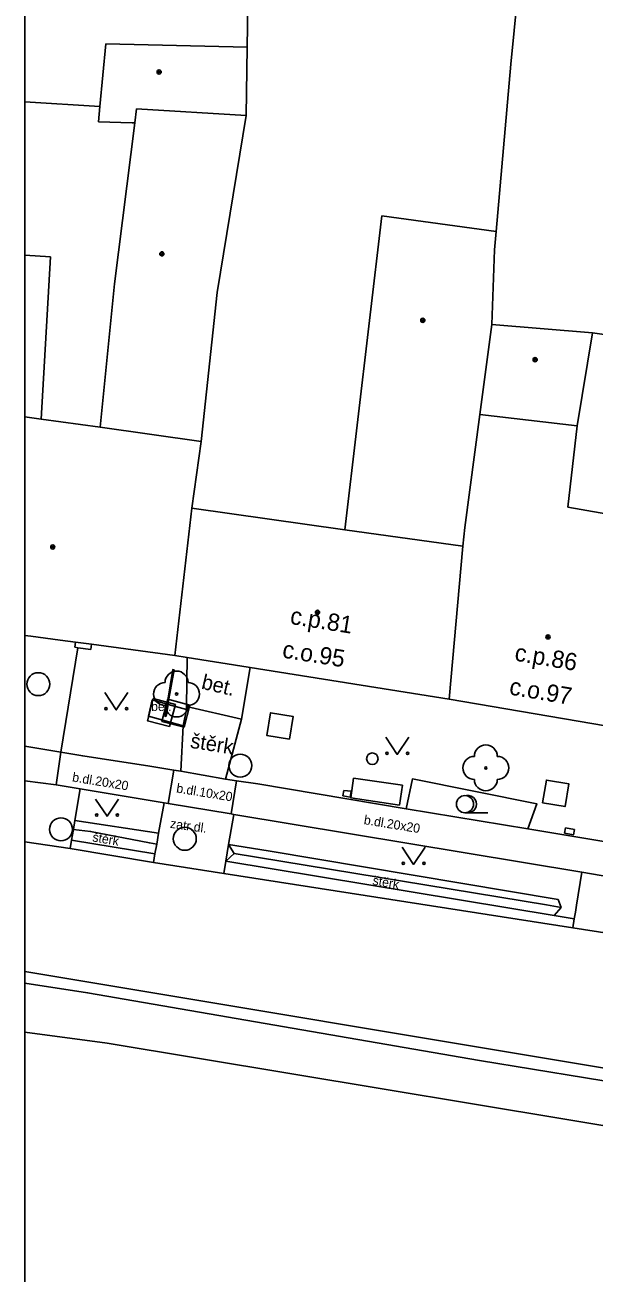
# Model space of a CAD drawing. Extents: x -591353 to -591106, y -1167325 to -1167155.
# Drawn here: x -591352.6 to -591327.7, y -1167266.9 to -1167212.5 of the extents above; entities that cross this region are included whole.
import ezdxf

# ---------------------------------------------------------------- set-up
doc = ezdxf.new("R2010")
doc.units = 0
for name, color, linetype in [('Level 22', 7, 'Continuous'), ('Level 24', 7, 'Continuous'), ('Level 26', 7, 'Continuous'), ('Level 27', 7, 'Continuous'), ('Level 31', 7, 'Continuous'), ('Level 36', 7, 'Continuous'), ('Level 39', 7, 'Continuous'), ('Vrstva 10', 7, 'Continuous'), ('Vrstva 11', 7, 'Continuous'), ('Vrstva 21', 7, 'Continuous'), ('Vrstva 40', 7, 'Continuous'), ('Vrstva 46', 7, 'Continuous'), ('Vrstva 5', 7, 'Continuous'), ('Vrstva 51', 7, 'Continuous'), ('Vrstva 6', 7, 'Continuous'), ('Vrstva 63', 7, 'Continuous'), ('Vrstva 7', 7, 'Continuous')]:
    doc.layers.add(name, color=color, linetype=linetype)

msp = doc.modelspace()

# ---------------------------------------------------------------- linework, layer by layer
at = {"layer": 'Level 22'}
for centre in [(-591345.96, -1167241.69), (-591332.47, -1167244.91)]:
    msp.add_circle(centre, 0.05, dxfattribs=at)
for centre, start, end in [((-591345.96, -1167241.19), 0, 180), ((-591346.46, -1167241.69), 90, 270), ((-591345.46, -1167241.69), 270, 90), ((-591345.96, -1167242.19), 180, 0), ((-591332.47, -1167244.41), 0, 180), ((-591332.97, -1167244.91), 90, 270), ((-591331.97, -1167244.91), 270, 90), ((-591332.47, -1167245.41), 180, 0)]:
    msp.add_arc(centre, 0.5, start, end, dxfattribs=at)
at = {"layer": 'Level 24'}
for points in [[(-591350.4, -1167239.65), (-591350.37, -1167239.43)], [(-591350.4, -1167239.65), (-591350.27, -1167239.67)], [(-591350.27, -1167239.67), (-591349.7, -1167239.75)], [(-591349.7, -1167239.75), (-591349.67, -1167239.52)], [(-591338.24, -1167245.36), (-591338.36, -1167246.22)], [(-591338.24, -1167245.36), (-591336.1, -1167245.67)], [(-591336.1, -1167245.67), (-591336.23, -1167246.53)], [(-591338.7, -1167246.13), (-591338.66, -1167245.89)], [(-591338.7, -1167246.13), (-591338.38, -1167246.18)], [(-591338.66, -1167245.89), (-591338.34, -1167245.93)], [(-591338.38, -1167246.18), (-591338.34, -1167245.93)], [(-591338.36, -1167246.22), (-591336.23, -1167246.53)], [(-591329, -1167247.53), (-591329.04, -1167247.76)], [(-591329.04, -1167247.76), (-591328.64, -1167247.83)], [(-591329, -1167247.53), (-591328.6, -1167247.6)], [(-591328.6, -1167247.6), (-591328.64, -1167247.83)]]:
    msp.add_lwpolyline(points, dxfattribs=at)
at = {"layer": 'Level 26'}
for points in [[(-591346.264, -1167243.111), (-591346.009, -1167242.144), (-591346.976, -1167241.889), (-591347.231, -1167242.856)], [(-591345.634, -1167243.141), (-591345.379, -1167242.174), (-591346.346, -1167241.919), (-591346.601, -1167242.886)], [(-591341.039, -1167243.656), (-591340.874, -1167242.669), (-591341.861, -1167242.504), (-591342.026, -1167243.491)], [(-591329.996, -1167246.43), (-591329.01, -1167246.596), (-591328.844, -1167245.61), (-591329.83, -1167245.444)]]:
    msp.add_lwpolyline(points, close=True, dxfattribs=at)
at = {"layer": 'Level 27'}
for centre in [(-591351.99, -1167241.26), (-591343.18, -1167244.81), (-591351, -1167247.59), (-591345.6, -1167248)]:
    msp.add_circle(centre, 0.5, dxfattribs=at)
at = {"layer": 'Level 31'}
msp.add_circle((-591337.42, -1167244.51), 0.25, dxfattribs=at)
at = {"layer": 'Level 36'}
msp.add_line((-591333.38, -1167246.865), (-591332.38, -1167246.865), dxfattribs=at)
for points in [[(-591349.09, -1167241.63), (-591348.59, -1167242.38), (-591348.09, -1167241.63)], [(-591336.83, -1167243.57), (-591336.33, -1167244.32), (-591335.83, -1167243.57)], [(-591349.49, -1167246.27), (-591348.99, -1167247.02), (-591348.49, -1167246.27)], [(-591336.12, -1167248.37), (-591335.62, -1167249.12), (-591335.12, -1167248.37)]]:
    msp.add_lwpolyline(points, dxfattribs=at)
for centre, radius in [((-591349.04, -1167242.33), 0.05), ((-591348.141, -1167242.33), 0.05), ((-591336.78, -1167244.27), 0.05), ((-591335.881, -1167244.27), 0.05), ((-591333.38, -1167246.49), 0.375), ((-591349.44, -1167246.97), 0.05), ((-591348.541, -1167246.97), 0.05), ((-591336.07, -1167249.07), 0.05), ((-591335.171, -1167249.07), 0.05)]:
    msp.add_circle(centre, radius, dxfattribs=at)
msp.add_arc((-591333.255, -1167246.49), 0.375, 260.4059, 99.5941, dxfattribs=at)
at = {"layer": 'Level 39'}
for centre, radius in [((-591346.72, -1167214.57), 0.09), ((-591346.72, -1167214.57), 0.0398), ((-591346.6, -1167222.5), 0.09), ((-591346.6, -1167222.5), 0.0398), ((-591335.22, -1167225.4), 0.09), ((-591335.22, -1167225.4), 0.0398), ((-591330.32, -1167227.11), 0.09), ((-591330.32, -1167227.11), 0.0398), ((-591351.36, -1167235.28), 0.09), ((-591351.36, -1167235.28), 0.0398), ((-591339.81, -1167238.13), 0.09), ((-591339.81, -1167238.13), 0.0398), ((-591329.76, -1167239.2), 0.09), ((-591329.76, -1167239.2), 0.0398)]:
    msp.add_circle(centre, radius, dxfattribs=at)
at = {"layer": 'Vrstva 10'}
for p, q in [((-591350.6, -1167248.43), (-591352.572, -1167248.129)), ((-591352.572, -1167253.793), (-591321.23, -1167259.02))]:
    msp.add_line(p, q, dxfattribs=at)
for points in [[(-591346.97, -1167249.04), (-591350.6, -1167248.43)], [(-591343.9, -1167249.51), (-591346.97, -1167249.04)], [(-591328.67, -1167251.89), (-591343.9, -1167249.51)], [(-591323.92, -1167252.63), (-591328.67, -1167251.89)]]:
    msp.add_lwpolyline(points, dxfattribs=at)
at = {"layer": 'Vrstva 11'}
for p, q in [((-591352.572, -1167243.964), (-591351.01, -1167244.23)), ((-591351.21, -1167245.65), (-591352.572, -1167245.475))]:
    msp.add_line(p, q, dxfattribs=at)
for points in [[(-591352.572, -1167222.555), (-591351.461, -1167222.633), (-591351.87, -1167229.7)], [(-591350.27, -1167239.67), (-591351.01, -1167244.23)], [(-591345.5, -1167240.09), (-591345.52, -1167242.23)], [(-591346.07, -1167240.64), (-591346.125, -1167240.626), (-591346.36, -1167242.05), (-591346.37, -1167242.13)], [(-591342.75, -1167240.53), (-591343.13, -1167242.79)], [(-591347.03, -1167241.95), (-591347.18, -1167242.65)], [(-591347.03, -1167241.95), (-591346.37, -1167242.13)], [(-591346.37, -1167242.13), (-591346.463, -1167242.657), (-591346.41, -1167242.67)], [(-591346.33, -1167242.14), (-591345.52, -1167242.36)], [(-591345.52, -1167242.36), (-591345.67, -1167243.07)], [(-591345.52, -1167242.23), (-591345.52, -1167242.36)], [(-591345.52, -1167242.23), (-591343.13, -1167242.79)], [(-591347.18, -1167242.65), (-591345.67, -1167243.07)], [(-591345.78, -1167245.06), (-591345.67, -1167243.07)], [(-591343.13, -1167242.79), (-591343.83, -1167245.4)], [(-591351.01, -1167244.23), (-591351.21, -1167245.65)], [(-591351.01, -1167244.23), (-591350.05, -1167244.39), (-591347.13, -1167244.84), (-591346.08, -1167245.01)], [(-591346.32, -1167246.46), (-591346.08, -1167245.01)], [(-591346.08, -1167245.01), (-591345.78, -1167245.06)], [(-591345.78, -1167245.06), (-591343.83, -1167245.4)], [(-591351.21, -1167245.65), (-591350.16, -1167245.83)], [(-591350.4, -1167247.21), (-591350.16, -1167245.83)], [(-591350.16, -1167245.83), (-591346.5, -1167246.43)], [(-591343.34, -1167245.48), (-591343.83, -1167245.4)], [(-591343.34, -1167245.48), (-591343.58, -1167246.92)], [(-591335.95, -1167246.69), (-591342.42, -1167245.61), (-591343.34, -1167245.48)], [(-591346.5, -1167246.43), (-591346.74, -1167247.76)], [(-591346.5, -1167246.43), (-591346.32, -1167246.46)], [(-591346.32, -1167246.46), (-591343.58, -1167246.92)], [(-591343.69, -1167248.25), (-591343.46, -1167246.94)], [(-591343.58, -1167246.92), (-591343.46, -1167246.94)], [(-591343.46, -1167246.94), (-591328.28, -1167249.46)], [(-591330.64, -1167247.57), (-591335.95, -1167246.69)], [(-591350.46, -1167247.59), (-591350.4, -1167247.21)], [(-591346.74, -1167247.76), (-591350.4, -1167247.21)], [(-591350.54, -1167248.06), (-591350.46, -1167247.59)], [(-591346.82, -1167248.24), (-591347.14, -1167248.18), (-591349.71, -1167247.68), (-591350.46, -1167247.59)], [(-591346.74, -1167247.76), (-591346.82, -1167248.24)], [(-591326.45, -1167248.27), (-591330.64, -1167247.57)], [(-591350.6, -1167248.43), (-591350.54, -1167248.06)], [(-591350.54, -1167248.06), (-591346.9, -1167248.66)], [(-591346.82, -1167248.24), (-591346.9, -1167248.66)], [(-591343.81, -1167248.98), (-591343.69, -1167248.25)], [(-591343.45, -1167248.64), (-591343.69, -1167248.25)], [(-591343.69, -1167248.25), (-591341.96, -1167248.53), (-591329.32, -1167250.65), (-591329.19, -1167251)], [(-591346.9, -1167248.66), (-591346.97, -1167249.04)], [(-591343.9, -1167249.51), (-591343.81, -1167248.98)], [(-591343.45, -1167248.64), (-591343.81, -1167248.98)], [(-591343.81, -1167248.98), (-591329.49, -1167251.35)], [(-591343.45, -1167248.64), (-591329.83, -1167250.88), (-591329.19, -1167251)], [(-591328.28, -1167249.46), (-591328.51, -1167250.89)], [(-591328.28, -1167249.46), (-591326.68, -1167249.73)], [(-591329.19, -1167251), (-591329.49, -1167251.35)], [(-591328.56, -1167251.2), (-591328.61, -1167251.49)], [(-591328.51, -1167250.89), (-591328.56, -1167251.2)], [(-591329.49, -1167251.35), (-591328.61, -1167251.49)], [(-591328.61, -1167251.49), (-591328.67, -1167251.89)], [(-591321.18, -1167259.55), (-591332.74, -1167257.67), (-591349.84, -1167254.71), (-591352.572, -1167254.294)], [(-591352.572, -1167256.425), (-591348.99, -1167256.91), (-591320.97, -1167261.56)]]:
    msp.add_lwpolyline(points, dxfattribs=at)
at = {"layer": 'Vrstva 21'}
msp.add_lwpolyline([(-591335.95, -1167246.69), (-591335.67, -1167245.39), (-591330.24, -1167246.48), (-591330.64, -1167247.57)], dxfattribs=at)
at = {"layer": 'Vrstva 5'}
for p, q in [((-591351.87, -1167229.7), (-591352.572, -1167229.602)), ((-591352.572, -1167239.136), (-591352.32, -1167239.17))]:
    msp.add_line(p, q, dxfattribs=at)
for points in [[(-591349.05, -1167213.34), (-591349.31, -1167216.07)], [(-591342.88, -1167213.49), (-591349.05, -1167213.34)], [(-591342.93, -1167216.47), (-591342.88, -1167213.49)], [(-591349.31, -1167216.07), (-591349.37, -1167216.75)], [(-591347.7, -1167216.17), (-591347.78, -1167216.79)], [(-591342.93, -1167216.47), (-591347.7, -1167216.17)], [(-591344.19, -1167224.19), (-591342.93, -1167216.47)], [(-591349.37, -1167216.75), (-591347.9, -1167216.79)], [(-591347.78, -1167216.79), (-591348.67, -1167223.81)], [(-591347.9, -1167216.79), (-591347.78, -1167216.79)], [(-591337, -1167220.84), (-591338.62, -1167234.53)], [(-591332.02, -1167221.52), (-591337, -1167220.84)], [(-591332.09, -1167222.33), (-591332.02, -1167221.52)], [(-591332.21, -1167225.58), (-591332.09, -1167222.33)], [(-591348.67, -1167223.81), (-591349.29, -1167230.06)], [(-591344.89, -1167230.68), (-591344.19, -1167224.19)], [(-591332.73, -1167229.51), (-591332.21, -1167225.58)], [(-591327.82, -1167225.94), (-591332.21, -1167225.58)], [(-591328.48, -1167229.99), (-591327.82, -1167225.94)], [(-591333.39, -1167234.43), (-591332.73, -1167229.51)], [(-591332.73, -1167229.51), (-591328.48, -1167229.99)], [(-591349.29, -1167230.06), (-591351.87, -1167229.7)], [(-591344.89, -1167230.68), (-591349.29, -1167230.06)], [(-591328.48, -1167229.99), (-591328.9, -1167233.54)], [(-591345.3, -1167233.59), (-591344.89, -1167230.68)], [(-591345.3, -1167233.59), (-591346.03, -1167240.01)], [(-591345.3, -1167233.59), (-591338.62, -1167234.53)], [(-591328.9, -1167233.54), (-591324.66, -1167234.28)], [(-591333.47, -1167235.24), (-591333.39, -1167234.43)], [(-591338.62, -1167234.53), (-591333.47, -1167235.24)], [(-591333.47, -1167235.24), (-591334.07, -1167241.92)], [(-591351.04, -1167239.34), (-591350.37, -1167239.43)], [(-591350.37, -1167239.43), (-591349.67, -1167239.52)], [(-591349.67, -1167239.52), (-591346.03, -1167240.01)], [(-591346.03, -1167240.01), (-591345.5, -1167240.09)], [(-591342.83, -1167240.52), (-591342.75, -1167240.53)], [(-591342.75, -1167240.53), (-591334.07, -1167241.92)], [(-591334.07, -1167241.92), (-591327.84, -1167242.98)]]:
    msp.add_lwpolyline(points, dxfattribs=at)
at = {"layer": 'Vrstva 51'}
msp.add_line((-591352.572, -1167215.87), (-591349.31, -1167216.07), dxfattribs=at)
for points in [[(-591342.88, -1167213.49), (-591342.8, -1167208.93)], [(-591330.94, -1167209.81), (-591331.38, -1167214.23)], [(-591331.38, -1167214.23), (-591332.02, -1167221.52)], [(-591327.82, -1167225.94), (-591323.56, -1167226.55)]]:
    msp.add_lwpolyline(points, dxfattribs=at)
at = {"layer": 'Vrstva 6'}
for points in [[(-591352.32, -1167239.17), (-591351.04, -1167239.34)], [(-591345.5, -1167240.09), (-591342.83, -1167240.52)], [(-591327.84, -1167242.98), (-591326.57, -1167243.19)]]:
    msp.add_lwpolyline(points, dxfattribs=at)
at = {"layer": 'Vrstva 63'}
msp.add_lwpolyline([(-591352.572, -1167154.814), (-591106.035, -1167154.814), (-591106.035, -1167325.379), (-591352.572, -1167325.379)], close=True, dxfattribs=at)
at = {"layer": 'Vrstva 7'}
for points in [[(-591346.07, -1167240.64), (-591346.32, -1167242.06)], [(-591346.33, -1167242.14), (-591346.41, -1167242.67)], [(-591346.32, -1167242.06), (-591346.33, -1167242.14)]]:
    msp.add_lwpolyline(points, dxfattribs=at)

# ---------------------------------------------------------------- texts
at = {"layer": 'Vrstva 40'}
for s, height, rotation, p in [('bet.', 0.65, 346.7989, (-591344.91, -1167241.45)), ('štěrk', 0.65, 351.0123, (-591345.39, -1167244.03)), ('b.dl.20x20', 0.4, 350.7751, (-591350.53, -1167245.5)), ('b.dl.10x20', 0.4, 350.826, (-591345.99, -1167245.98)), ('b.dl.20x20', 0.4, 350.7751, (-591337.81, -1167247.36)), ('zatr.dl.', 0.4, 352, (-591346.26, -1167247.52)), ('štěrk', 0.4, 350.4518, (-591349.65, -1167248.11)), ('štěrk', 0.4, 350.4518, (-591337.43, -1167250))]:
    msp.add_text(s, height=height, rotation=rotation, dxfattribs=at).set_placement(p)
msp.add_text('bet.', height=0.4, dxfattribs=at).set_placement((-591347.07, -1167242.43))
at = {"layer": 'Vrstva 46'}
for s, rotation, p in [('c.p.81', 350.8805, (-591341.039, -1167238.628)), ('c.o.95', 350.8805, (-591341.379, -1167240.094)), ('c.p.86', 350.3578, (-591331.247, -1167240.227)), ('c.o.97', 350.3578, (-591331.48, -1167241.706))]:
    msp.add_text(s, height=0.75, rotation=rotation, dxfattribs=at).set_placement(p)

doc.saveas('drawing.dxf')
